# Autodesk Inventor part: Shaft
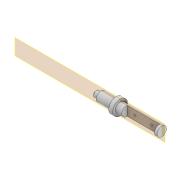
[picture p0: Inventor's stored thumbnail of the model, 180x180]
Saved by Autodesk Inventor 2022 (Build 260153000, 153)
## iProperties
Created: 2019-03
Part Number: Shaft
Material: Generic
Document SubType Name: Modeling
Designer: LENOVO-CADCIM
Density: 1 g/cm^3
Appearance: Default
Author: LENOVO-CADCIM
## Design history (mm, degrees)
sketch "Sketch1"
  geometry: L1 (284.311, 0)-(1023.188, 0); L2 (391.676, 0)-(391.676, -18); L3 (391.676, -18)-(420.576, -18); L4 (420.576, -18)-(420.576, -28); L5 (420.576, -28)-(510.376, -28); L6 (510.376, -28)-(510.376, -43.6); L7 (510.376, -43.6)-(534.376, -43.6); L8 (534.376, -43.6)-(534.376, -28); L9 (534.376, -28)-(781.476, -28); L10 (781.476, -28)-(781.476, 0); L11 (391.676, 0)-(781.476, 0); 1 further point
  constraints: 22 end point, 8 perpendicular, 5 point on line, 1 collinear, 1 horizontal
  dimensions: "d0" = 28.9 distance of L2.end L3.end; "d1" = 89.8 distance of L4.end L5.end; "d2" = 24 distance of L6.end L7.end; "d3" = 247.1 distance of L8.end L9.end; "d4" = 56 diameter of L9 L1; "d5" = 87.2 diameter of L7 L1; "d6" = 36 diameter of L3 L1
revolve "Revolution1" sketch "Sketch1" stored, may be unused: angle "d7" = 90 deg
sketch "Sketch4"
  geometry: L1 (-781.476, 28)-(-534.376, 28) reference; L2 (-572.576, 28)-(-766.376, 28); L3 (-766.376, 28)-(-766.376, -3.1); L4 (-766.376, -3.1)-(-572.576, -3.1); L5 (-572.576, -3.1)-(-572.576, 28); L6 (-781.476, -28)-(-534.376, -28) reference; 2 further points
  constraints: 8 end point, 2 parallel, 1 horizontal, 1 perpendicular, 1 point on line
  dimensions: "d16" = 24.9 distance between parallel lines of L6 L4; "d17" = 15.1 distance from line of L1.start L3; "d40" = 193.8 distance of L3.end L4.end
extrude "Extrusion3" cut sketch "Sketch4" stored distance "d18" = 257; taper "d19" = 0 deg
sketch "Sketch6"
  geometry: L1 (-180.9, 45.828)-(-180.9, 9.828) reference; L2 (-180.9, 27.828)-(320.546, 27.828); L3 (0, 55.828)-(0, -0.172) reference; 5 further points
  constraints: 2 end point, 2 point on line, 1 horizontal, 1 midpoint
  dimensions: "d24" = 100 distance of point (46.9, 27.828) point (146.9, 27.828); "d25" = 46.9 distance from line of L3 point (46.9, 27.828)
hole "Hole1" sketch "Sketch6" at (46.9, 27.828), (146.9, 27.828) diameter "d26" = 12.5; stored, may be unused: countersink angle "d30" = 90 deg, drill point angle "d32" = 118 deg; dims "d27" = 6, "d28" = 100, "d29" = 25, "d31" = 310
chamfer "Chamfer1" distance "d33" = 3; stored, may be unused: second distance "d34" = 2, angle "d35" = 45 deg
sketch "Sketch7"
  geometry: L1 (8, -22)-(-8, -22); L2 (-8, -22)-(-8, -26.833); L3 (8, -26.833)-(8, -22); L4 (0, 0)-(0, 64); C1 r 28 at (0, 0) reference; A1 r 28 centre (0, 0) between (-8, -26.833) and (8, -26.833); A2 r 28 centre (0, 0) between (8, -26.833) and (-8, -26.833) reference; 4 further points
  constraints: 8 end point, 3 point on circle, 1 centre point, 1 coincident, 1 concentric, 1 horizontal, 1 parallel, 1 perpendicular, 1 vertical, 1 other
  dimensions: "d36" = 16 distance between parallel lines of L3 L2; "d37" = 50 distance from line of point (0, 28) L1
extrude "Extrusion5" cut sketch "Sketch7" distance "d38" = 62.5; taper "d39" = 0 deg
body "Solid1"
